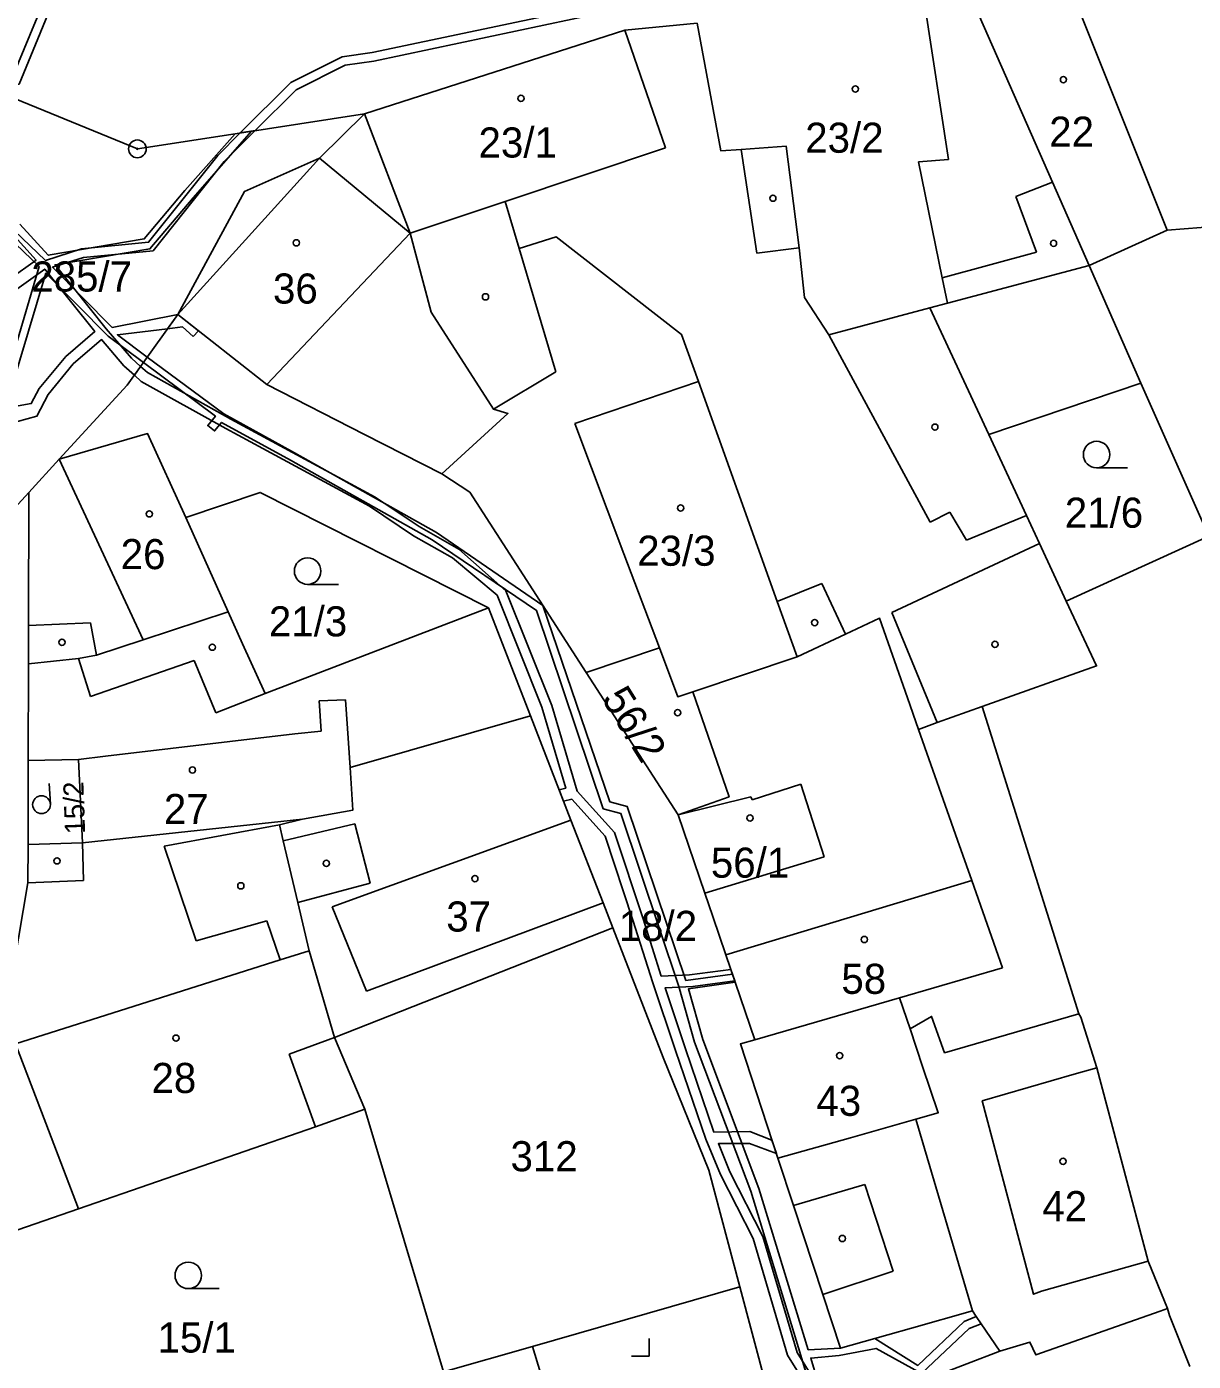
# Model space of a CAD drawing. Extents: x -779723 to -777378, y -1011169 to -1009297.
# Drawn here: x -779167.2 to -779101.4, y -1010377.1 to -1010301.7 of the extents above; entities that cross this region are included whole.
import ezdxf

# ---------------------------------------------------------------- set-up
doc = ezdxf.new("R2010")
doc.units = 0
for name, color, linetype in [('Hranice parcel', 7, 'Continuous'), ('Parcelní čísla', 7, 'Continuous'), ('Vnitřní kresba', 7, 'Continuous'), ('Věcná břemena k části', 7, 'Continuous'), ('Značky bodu BP', 7, 'Continuous'), ('Značky budov', 7, 'Continuous'), ('Značky kultur', 7, 'Continuous')]:
    doc.layers.add(name, color=color, linetype=linetype)

msp = doc.modelspace()

# ---------------------------------------------------------------- linework, layer by layer
at = {"layer": 'Hranice parcel'}
for p, q in [((-779148.16, -1010306.65), (-779145.58, -1010313.4)), ((-779104.32, -1010321.87), (-779107.24, -1010315.22)), ((-779112.91, -1010324.76), (-779104.32, -1010321.87)), ((-779100.48, -1010330.51), (-779104.32, -1010321.87)), ((-779165.4, -1010326.16), (-779167.12, -1010328.04)), ((-779155.86, -1010334.78), (-779158.26, -1010329.46)), ((-779100.48, -1010330.51), (-779108.53, -1010334.17)), ((-779138.79, -1010340.66), (-779141.16, -1010334.55)), ((-779129.62, -1010339.3), (-779123.73, -1010337.33)), ((-779167.14, -1010337.72), (-779167.15, -1010343.18)), ((-779135.65, -1010338.2), (-779130.45, -1010346.25)), ((-779107.81, -1010357.49), (-779113.27, -1010340.13)), ((-779167.15, -1010343.18), (-779167.16, -1010347.93)), ((-779164.08, -1010347.83), (-779151.66, -1010346.5)), ((-779164.08, -1010347.83), (-779167.16, -1010347.93)), ((-779149.85, -1010358.82), (-779134.14, -1010352.63)), ((-779127.75, -1010354.15), (-779126.12, -1010358.95)), ((-779148.14, -1010362.87), (-779149.85, -1010358.82)), ((-779143.7, -1010377.71), (-779148.14, -1010362.87)), ((-779125.49, -1010378.42), (-779126.96, -1010372.9))]:
    msp.add_line(p, q, dxfattribs=at)
for points in [[(-779107.24, -1010315.22), (-779102.83, -1010313.22), (-779096.1, -1010312.69), (-779092.74, -1010318.04), (-779088.64, -1010315.52), (-779088.67, -1010313.8), (-779087.34, -1010313.07), (-779081.53, -1010309.87), (-779087.9, -1010296.09), (-779090.04, -1010291.48)], [(-779113.91, -1010300.03), (-779109.3, -1010310.52), (-779107.24, -1010315.22)], [(-779129.38, -1010301.54), (-779133.45, -1010301.92), (-779148.16, -1010306.65)], [(-779112.91, -1010324.76), (-779116.23, -1010317.61), (-779121.94, -1010319.13), (-779123.32, -1010317.03), (-779123.62, -1010314.23), (-779124.34, -1010308.48), (-779126.89, -1010308.67), (-779128.03, -1010308.75), (-779129.38, -1010301.54)], [(-779169.61, -1010305.1), (-779160.99, -1010308.63), (-779155.46, -1010307.78), (-779148.16, -1010306.65)], [(-779148.16, -1010306.65), (-779150.7, -1010309.16), (-779154.94, -1010311.03), (-779158.7, -1010317.98)], [(-779145.58, -1010313.4), (-779142.02, -1010312.21), (-779140.22, -1010311.61), (-779139.43, -1010314.26), (-779137.34, -1010313.6), (-779130.26, -1010319.11), (-779129.3, -1010321.78), (-779124.85, -1010334.2), (-779123.73, -1010337.33)], [(-779145.58, -1010313.4), (-779144.39, -1010317.86), (-779140.88, -1010323.34), (-779140.06, -1010323.57), (-779143.8, -1010326.98)], [(-779158.7, -1010317.98), (-779161.56, -1010321.97), (-779165.4, -1010326.16)], [(-779158.7, -1010317.98), (-779153.68, -1010321.94), (-779148.16, -1010324.76), (-779143.8, -1010326.98)], [(-779158.26, -1010329.46), (-779160.41, -1010324.71), (-779165.4, -1010326.16)], [(-779108.53, -1010334.17), (-779110.04, -1010330.92), (-779110.78, -1010329.34), (-779112.91, -1010324.76)], [(-779143.8, -1010326.98), (-779142.22, -1010328.02), (-779135.65, -1010338.2)], [(-779172.68, -1010330.78), (-779170.22, -1010331.41), (-779167.12, -1010328.04)], [(-779167.12, -1010328.04), (-779167.14, -1010335.56), (-779167.14, -1010337.72)], [(-779158.26, -1010329.46), (-779154.05, -1010328.04), (-779141.16, -1010334.55)], [(-779141.16, -1010334.55), (-779153.78, -1010339.39), (-779155.05, -1010336.58), (-779155.86, -1010334.78)], [(-779113.27, -1010340.13), (-779106.82, -1010337.84), (-779108.53, -1010334.17)], [(-779167.14, -1010337.72), (-779164.32, -1010337.41), (-779163.3, -1010337.23), (-779160.66, -1010336.36), (-779155.86, -1010334.78)], [(-779123.73, -1010337.33), (-779120.99, -1010336.04), (-779119.07, -1010335.14), (-779117.5, -1010339.64), (-779116.88, -1010341.42)], [(-779135.65, -1010338.2), (-779131.51, -1010336.82), (-779130.47, -1010339.58), (-779129.62, -1010339.3)], [(-779129.62, -1010339.3), (-779127.57, -1010345.23), (-779130.45, -1010346.25)], [(-779151.66, -1010346.5), (-779148.82, -1010345.98), (-779148.98, -1010343.57), (-779138.79, -1010340.66)], [(-779134.14, -1010352.63), (-779134.69, -1010351.21), (-779136.5, -1010346.55), (-779138.79, -1010340.66)], [(-779116.88, -1010341.42), (-779115.81, -1010341.04), (-779113.27, -1010340.13)], [(-779127.75, -1010354.15), (-779113.87, -1010349.95), (-779114.67, -1010347.67), (-779116.88, -1010341.42)], [(-779167.15, -1010343.18), (-779164.31, -1010343.12), (-779164.08, -1010347.83)], [(-779149.85, -1010358.82), (-779151.29, -1010353.93), (-779151.93, -1010351.2), (-779152.75, -1010347.71), (-779152.96, -1010346.81), (-779151.66, -1010346.5)], [(-779130.45, -1010346.25), (-779128.94, -1010350.68), (-779128.49, -1010351.99), (-779127.75, -1010354.15)], [(-779167.16, -1010347.93), (-779167.17, -1010350.08), (-779168.77, -1010359.47), (-779169.76, -1010365.24), (-779170.69, -1010370.7)], [(-779134.14, -1010352.63), (-779131.3, -1010359.95), (-779128.72, -1010366.32), (-779126.96, -1010372.9)], [(-779117.35, -1010358.34), (-779117.94, -1010356.58), (-779126.12, -1010358.95)], [(-779107.81, -1010357.49), (-779115.4, -1010359.69), (-779116.13, -1010357.63), (-779117.35, -1010358.34)], [(-779102.81, -1010374.14), (-779103.91, -1010371.45), (-779106.8, -1010360.53), (-779107.71, -1010357.68), (-779107.81, -1010357.49)], [(-779117.35, -1010358.34), (-779116.64, -1010360.46), (-779115.76, -1010363.08), (-779117.03, -1010363.44), (-779113.83, -1010374.27)], [(-779126.12, -1010358.95), (-779126.93, -1010359.19), (-779124.81, -1010365.65), (-779123.93, -1010368.31), (-779122.28, -1010373.34), (-779121.28, -1010376.38), (-779117.26, -1010375.24), (-779113.83, -1010374.27)], [(-779170.69, -1010370.7), (-779164.31, -1010368.5), (-779150.92, -1010363.88), (-779148.14, -1010362.87)], [(-779126.96, -1010372.9), (-779138.68, -1010376.27), (-779143.7, -1010377.71)], [(-779113.83, -1010374.27), (-779113.61, -1010374.59), (-779113.33, -1010375), (-779112.28, -1010376.55)], [(-779102.81, -1010374.14), (-779103.23, -1010374.29), (-779110.25, -1010376.75), (-779110.58, -1010376.03), (-779112.28, -1010376.55)], [(-779101.55, -1010377.4), (-779102.69, -1010374.53), (-779102.81, -1010374.14)], [(-779112.28, -1010376.55), (-779116, -1010377.97), (-779121.56, -1010379.84), (-779120.97, -1010381.67), (-779117.8, -1010390.87)]]:
    msp.add_lwpolyline(points, dxfattribs=at)
at = {"layer": 'Vnitřní kresba'}
for p, q in [((-779108.85, -1010298.16), (-779102.83, -1010313.22)), ((-779116.55, -1010300.26), (-779115.17, -1010309.24)), ((-779133.45, -1010301.92), (-779131.16, -1010308.58)), ((-779140.22, -1010311.61), (-779131.16, -1010308.58)), ((-779126.89, -1010308.67), (-779126, -1010314.52)), ((-779158.7, -1010317.98), (-779150.7, -1010309.16)), ((-779150.7, -1010309.16), (-779145.58, -1010313.4)), ((-779115.17, -1010309.24), (-779116.88, -1010309.36)), ((-779116.88, -1010309.36), (-779115.53, -1010315.91)), ((-779111.38, -1010311.33), (-779109.3, -1010310.52)), ((-779110.21, -1010314.47), (-779111.38, -1010311.33)), ((-779153.68, -1010321.94), (-779145.58, -1010313.4)), ((-779137.35, -1010321.23), (-779139.43, -1010314.26)), ((-779126, -1010314.52), (-779123.62, -1010314.23)), ((-779115.53, -1010315.91), (-779110.21, -1010314.47)), ((-779115.23, -1010317.34), (-779107.24, -1010315.22)), ((-779115.53, -1010315.91), (-779115.23, -1010317.34)), ((-779116.23, -1010317.61), (-779115.23, -1010317.34)), ((-779121.94, -1010319.13), (-779116.22, -1010329.71)), ((-779137.35, -1010321.23), (-779140.88, -1010323.34)), ((-779136.29, -1010324.15), (-779129.3, -1010321.78)), ((-779136.29, -1010324.15), (-779133.52, -1010331.51)), ((-779165.4, -1010326.16), (-779160.66, -1010336.36)), ((-779116.22, -1010329.71), (-779115.11, -1010329.15)), ((-779115.11, -1010329.15), (-779114.16, -1010330.74)), ((-779114.16, -1010330.74), (-779110.78, -1010329.34)), ((-779133.52, -1010331.51), (-779131.51, -1010336.82)), ((-779118.38, -1010334.82), (-779110.04, -1010330.92)), ((-779124.85, -1010334.2), (-779122.33, -1010333.18)), ((-779122.33, -1010333.18), (-779120.99, -1010336.04)), ((-779167.14, -1010335.56), (-779163.63, -1010335.4)), ((-779163.63, -1010335.4), (-779163.3, -1010337.23)), ((-779118.38, -1010334.82), (-779115.81, -1010341.04)), ((-779164.32, -1010337.41), (-779163.63, -1010339.56)), ((-779163.63, -1010339.56), (-779157.78, -1010337.53)), ((-779157.78, -1010337.53), (-779156.56, -1010340.49)), ((-779153.78, -1010339.39), (-779156.56, -1010340.49)), ((-779149.23, -1010339.75), (-779150.73, -1010339.81)), ((-779150.73, -1010339.81), (-779150.61, -1010341.52)), ((-779149.23, -1010339.75), (-779149.12, -1010341.37)), ((-779149.12, -1010341.37), (-779148.98, -1010343.57)), ((-779162.78, -1010342.94), (-779152.1, -1010341.68)), ((-779152.1, -1010341.68), (-779150.61, -1010341.52)), ((-779164.31, -1010343.12), (-779162.78, -1010342.94)), ((-779126.27, -1010345.4), (-779123.51, -1010344.52)), ((-779123.51, -1010344.52), (-779122.2, -1010348.62)), ((-779130.45, -1010346.25), (-779126.34, -1010345.23)), ((-779126.34, -1010345.23), (-779126.27, -1010345.4)), ((-779149.98, -1010351.45), (-779136.5, -1010346.55)), ((-779159.47, -1010348.01), (-779152.96, -1010346.81)), ((-779152.75, -1010347.71), (-779148.71, -1010346.75)), ((-779148.71, -1010346.75), (-779147.85, -1010350.1)), ((-779164.08, -1010347.83), (-779164.04, -1010349.95)), ((-779159.47, -1010348.01), (-779157.66, -1010353.36)), ((-779122.2, -1010348.62), (-779128.94, -1010350.68)), ((-779167.17, -1010350.08), (-779164.04, -1010349.95)), ((-779151.93, -1010351.2), (-779147.85, -1010350.1)), ((-779113.87, -1010349.95), (-779112.12, -1010354.89)), ((-779148.04, -1010356.21), (-779134.69, -1010351.21)), ((-779149.98, -1010351.45), (-779148.04, -1010356.21)), ((-779157.66, -1010353.36), (-779153.67, -1010352.23)), ((-779153.67, -1010352.23), (-779152.93, -1010354.43)), ((-779151.29, -1010353.93), (-779152.93, -1010354.43)), ((-779152.93, -1010354.43), (-779167.87, -1010359.19)), ((-779117.94, -1010356.58), (-779112.12, -1010354.89)), ((-779167.87, -1010359.19), (-779166.01, -1010364.05)), ((-779152.41, -1010359.76), (-779149.85, -1010358.82)), ((-779152.41, -1010359.76), (-779150.92, -1010363.88)), ((-779120.72, -1010364.49), (-779117.03, -1010363.44)), ((-779166.01, -1010364.05), (-779164.31, -1010368.5)), ((-779124.81, -1010365.65), (-779120.72, -1010364.49)), ((-779123.93, -1010368.31), (-779119.9, -1010367.12)), ((-779119.9, -1010367.12), (-779118.3, -1010372.03)), ((-779118.3, -1010372.03), (-779122.28, -1010373.34)), ((-779136.94, -1010381.93), (-779138.68, -1010376.27))]:
    msp.add_line(p, q, dxfattribs=at)
msp.add_lwpolyline([(-779106.8, -1010360.53), (-779108.08, -1010360.89), (-779113.27, -1010362.41), (-779110.38, -1010373.33), (-779109.92, -1010373.16), (-779103.91, -1010371.45)], dxfattribs=at)
at = {"layer": 'Věcná břemena k části'}
for points in [[(-779165.25, -1010299.1), (-779165.69, -1010298.88), (-779168.03, -1010304.53), (-779169.81, -1010304.95), (-779169.61, -1010305.1), (-779168.76, -1010305.45), (-779168.92, -1010305.23), (-779167.67, -1010304.97)], [(-779124.64, -1010300.11), (-779122.56, -1010299.49), (-779133.3, -1010300.13), (-779147.73, -1010303.19), (-779149.42, -1010303.43), (-779152.32, -1010304.88), (-779155.18, -1010307.73), (-779154.33, -1010307.6), (-779152.02, -1010305.3), (-779149.26, -1010303.91), (-779147.64, -1010303.68), (-779133.24, -1010300.63)], [(-779157.83, -1010319.23), (-779157.53, -1010318.9), (-779158.7, -1010317.98), (-779159.28, -1010318.79), (-779158.44, -1010318.69)]]:
    msp.add_lwpolyline(points, close=True, dxfattribs=at)
for points in [[(-779168.61, -1010323.84), (-779166.16, -1010315.66), (-779162.64, -1010319.21), (-779160.65, -1010320.7), (-779160.43, -1010320.39), (-779162.12, -1010319.13), (-779159.28, -1010318.79), (-779158.7, -1010317.98), (-779162.42, -1010318.72), (-779165.79, -1010315.32), (-779164.04, -1010314.77), (-779160.1, -1010314.39), (-779156.08, -1010309.34), (-779154.33, -1010307.6), (-779155.18, -1010307.73), (-779156.45, -1010309), (-779160.36, -1010313.91), (-779164.14, -1010314.27), (-779166.18, -1010314.93), (-779171.03, -1010310.31)], [(-779168.3, -1010324.18), (-779166.66, -1010323.72), (-779166.03, -1010322.5), (-779164.61, -1010320.78), (-779163.01, -1010319.4), (-779161.76, -1010320.88), (-779161.16, -1010321.42), (-779160.81, -1010320.92), (-779161.32, -1010320.46), (-779162.75, -1010318.79), (-779165.64, -1010315.18), (-779160.28, -1010314.28), (-779157.84, -1010311.39), (-779154.54, -1010307.63), (-779155.46, -1010307.78), (-779158.3, -1010310.99), (-779160.6, -1010313.72), (-779166.02, -1010314.64), (-779167.62, -1010312.88)], [(-779171.41, -1010310.63), (-779166.54, -1010315.27), (-779169.04, -1010323.72)], [(-779168.1, -1010313.38), (-779166.71, -1010314.91), (-779168.2, -1010315.98)], [(-779167.79, -1010316.55), (-779166.22, -1010315.42), (-779163.39, -1010318.94), (-779165.03, -1010320.36), (-779166.53, -1010322.16), (-779166.98, -1010323.02), (-779169.01, -1010323.38)], [(-779122.99, -1010377.81), (-779123.73, -1010376.61), (-779125.67, -1010370.07), (-779127.53, -1010366.41), (-779128.17, -1010364.82), (-779126.41, -1010364.81), (-779124.9, -1010365.38), (-779125.15, -1010364.62), (-779126.39, -1010364.14), (-779128.43, -1010364.17), (-779130.04, -1010359.46), (-779131.19, -1010356.02), (-779129.62, -1010355.95), (-779127.25, -1010355.62), (-779127.47, -1010354.98), (-779129.8, -1010355.29), (-779131.4, -1010355.36), (-779132.42, -1010352.12), (-779134.04, -1010347.25), (-779136.16, -1010344.91), (-779137.58, -1010340.07), (-779140.18, -1010333.59), (-779142.83, -1010331.24), (-779145.08, -1010329.96), (-779147.56, -1010328.3), (-779153.62, -1010325.03), (-779155.71, -1010323.9), (-779160.41, -1010321.27), (-779160.81, -1010320.92), (-779161.16, -1010321.42), (-779160.77, -1010321.77), (-779155.99, -1010324.42), (-779153.9, -1010325.55), (-779147.88, -1010328.82), (-779145.4, -1010330.48), (-779143.19, -1010331.74), (-779140.67, -1010333.84), (-779138.14, -1010340.16), (-779136.8, -1010344.75), (-779137.17, -1010344.83), (-779136.92, -1010345.48), (-779136.46, -1010345.37), (-779134.56, -1010347.46), (-779133, -1010352.19), (-779131.87, -1010355.74), (-779130.59, -1010359.55), (-779128.89, -1010364.56), (-779128.06, -1010366.56), (-779126.22, -1010370.18), (-779124.28, -1010376.76), (-779123.56, -1010377.92)], [(-779122.04, -1010380.04), (-779122.96, -1010376.93), (-779121.35, -1010376.78), (-779119.27, -1010376.39), (-779116.7, -1010377.8), (-779114.02, -1010375.27), (-779113.33, -1010375), (-779113.61, -1010374.59), (-779114.29, -1010374.86), (-779116.91, -1010377.35), (-779119.33, -1010375.83), (-779121.28, -1010376.38), (-779123.1, -1010376.46), (-779125.9, -1010367.35), (-779129.06, -1010358.94), (-779129.87, -1010356.07), (-779127.22, -1010355.7), (-779127.38, -1010355.25), (-779130.01, -1010355.6), (-779133.32, -1010345.78), (-779134.3, -1010345.51), (-779138.09, -1010334.42), (-779144.09, -1010330.3), (-779152.11, -1010325.8), (-779156.11, -1010323.59), (-779160.43, -1010320.39), (-779160.65, -1010320.7), (-779156.58, -1010323.73), (-779157.01, -1010324.26), (-779156.63, -1010324.56), (-779156.23, -1010324.08), (-779152.35, -1010326.22), (-779144.34, -1010330.71), (-779138.45, -1010334.7), (-779134.68, -1010345.9), (-779133.69, -1010346.17), (-779130.4, -1010355.94), (-779129.52, -1010359.08), (-779126.34, -1010367.5), (-779123.51, -1010376.79), (-779122.46, -1010380.32)]]:
    msp.add_lwpolyline(points, dxfattribs=at)
at = {"layer": 'Značky bodu BP'}
for radius in [0.5, 0.0303]:
    msp.add_circle((-779160.99, -1010308.63), radius, dxfattribs=at)
at = {"layer": 'Značky budov'}
for centre in [(-779120.437, -1010305.249), (-779108.687, -1010304.719), (-779139.327, -1010305.779), (-779125.097, -1010311.419), (-779152.007, -1010313.939), (-779109.247, -1010313.969), (-779141.327, -1010316.989), (-779115.947, -1010324.349), (-779160.317, -1010329.249), (-779130.307, -1010328.919), (-779122.737, -1010335.389), (-779165.247, -1010336.499), (-779156.757, -1010336.779), (-779112.557, -1010336.619), (-779130.477, -1010340.479), (-779157.877, -1010343.719), (-779126.387, -1010346.429), (-779165.527, -1010348.849), (-779150.317, -1010348.989), (-779141.927, -1010349.849), (-779155.147, -1010350.259), (-779119.937, -1010353.289), (-779158.807, -1010358.859), (-779121.327, -1010359.849), (-779108.707, -1010365.819), (-779121.177, -1010370.179)]:
    msp.add_circle(centre, 0.175, dxfattribs=at)
at = {"layer": 'Značky kultur'}
for p, q in [((-779106.813, -1010326.65), (-779105.063, -1010326.65)), ((-779151.373, -1010333.23), (-779149.623, -1010333.23)), ((-779165.9, -1010345.645), (-779165.962, -1010344.474)), ((-779158.113, -1010373.01), (-779156.363, -1010373.01)), ((-779132.08, -1010376.83), (-779132.08, -1010375.83)), ((-779133.081, -1010376.83), (-779132.08, -1010376.83))]:
    msp.add_line(p, q, dxfattribs=at)
for centre, radius in [((-779106.813, -1010325.9), 0.75), ((-779151.373, -1010332.48), 0.75), ((-779166.402, -1010345.672), 0.502), ((-779158.113, -1010372.26), 0.75)]:
    msp.add_circle(centre, radius, dxfattribs=at)

# ---------------------------------------------------------------- texts
at = {"layer": 'Parcelní čísla'}
for s, p in [('23/1', (-779141.72, -1010309.12)), ('23/2', (-779123.27, -1010308.85)), ('22', (-779109.49, -1010308.51)), ('285/7', (-779166.98, -1010316.69)), ('36', (-779153.33, -1010317.37)), ('21/6', (-779108.61, -1010330.03)), ('26', (-779161.932, -1010332.37)), ('23/3', (-779132.76, -1010332.179)), ('21/3', (-779153.561, -1010336.169)), ('27', (-779159.492, -1010346.77)), ('56/1', (-779128.6, -1010349.799)), ('37', (-779143.542, -1010352.84)), ('18/2', (-779133.801, -1010353.37)), ('58', (-779121.23, -1010356.36)), ('28', (-779160.192, -1010361.96)), ('43', (-779122.64, -1010363.25)), ('312', (-779139.914, -1010366.38)), ('42', (-779109.88, -1010369.2)), ('15/1', (-779159.85, -1010376.62))]:
    msp.add_text(s, height=1.7, dxfattribs=at).set_placement(p)
for s, height, rotation, p in [('56/2', 1.7, 302, (-779134.81, -1010339.68)), ('15/2', 1.14, 92, (-779163.937, -1010347.311))]:
    msp.add_text(s, height=height, rotation=rotation, dxfattribs=at).set_placement(p)

doc.saveas('drawing.dxf')
